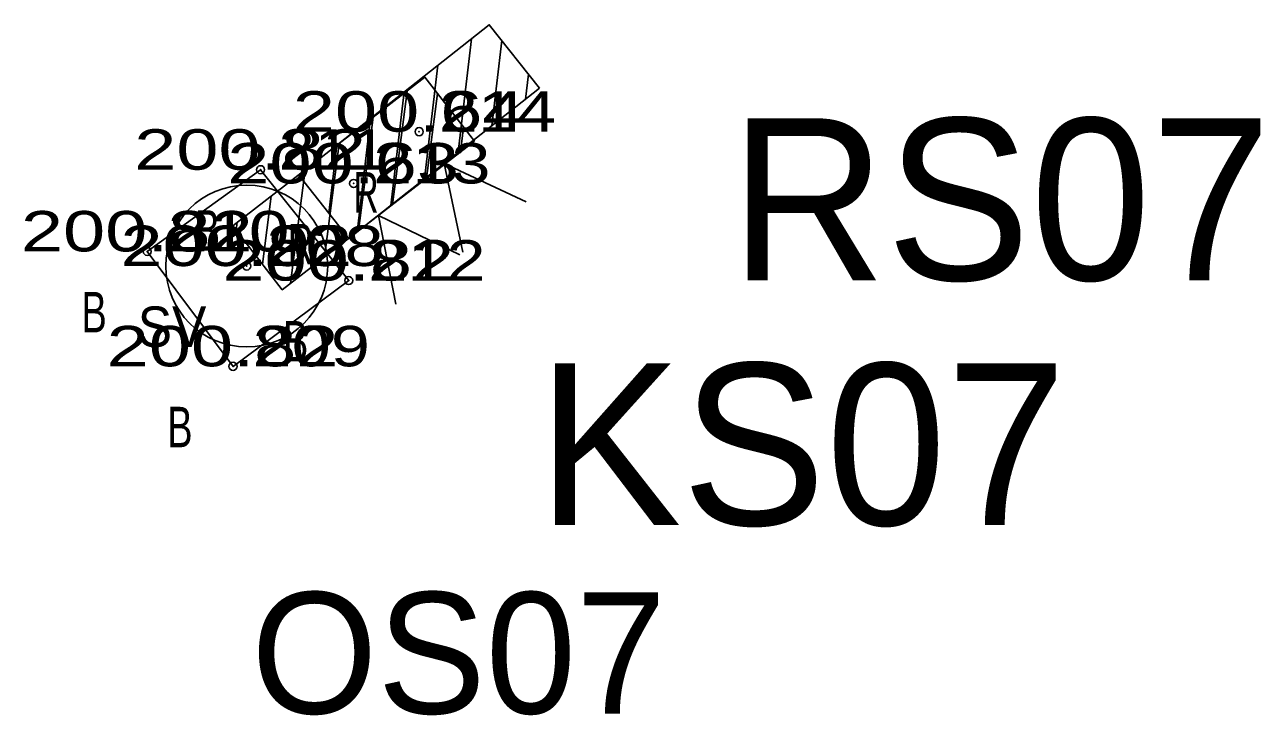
# Model space of a CAD drawing. Extents: x -465254 to -463400, y -1095454 to -1094005.
# Drawn here: x -465102.15 to -465086.89, y -1095346.43 to -1095337.9 of the extents above; entities that cross this region are included whole.
import ezdxf
from ezdxf.enums import TextEntityAlignment as Align

# ---------------------------------------------------------------- set-up
doc = ezdxf.new("R2010")
doc.units = 0
doc.header["$LTSCALE"] = 0.2
doc.header["$PDMODE"] = 32
doc.header["$PDSIZE"] = 0.1
for name, color, linetype in [('1', 7, 'Continuous'), ('2', 7, 'Continuous'), ('3', 7, 'Continuous'), ('4', 7, 'Continuous')]:
    doc.layers.add(name, color=color, linetype=linetype)
for name, color, linetype, lineweight in [('12', 7, 'Continuous', 25), ('25', 7, 'Continuous', 25), ('33', 7, 'Continuous', 25)]:
    doc.layers.add(name, color=color, linetype=linetype, lineweight=lineweight)

msp = doc.modelspace()

# ---------------------------------------------------------------- linework, layer by layer
at = {"layer": '1'}
for p in [(-465097.28, -1095339.22), (-465099.24, -1095339.69), (-465098.09, -1095339.86), (-465100.64, -1095340.7), (-465099.41, -1095340.88), (-465098.15, -1095341.06), (-465099.58, -1095342.12)]:
    msp.add_point(p, dxfattribs=at)
at = {"layer": '12'}
msp.add_lwpolyline([(-465099.24, -1095339.69), (-465098.15, -1095341.06), (-465099.58, -1095342.12), (-465100.64, -1095340.7)], close=True, dxfattribs=at)
at = {"layer": '25'}
msp.add_circle((-465099.41, -1095340.88), 1, dxfattribs=at)
at = {"layer": '33'}
for p, q in [((-465096.632, -1095338.071), (-465096.797, -1095339.475)), ((-465096.257, -1095338.095), (-465096.38, -1095339.146)), ((-465097.048, -1095338.399), (-465097.212, -1095339.804)), ((-465095.928, -1095338.511), (-465095.964, -1095338.818)), ((-465097.464, -1095338.728), (-465097.628, -1095340.132)), ((-465097.43, -1095338.718), (-465097.609, -1095340.121)), ((-465097.055, -1095338.747), (-465097.189, -1095339.796)), ((-465097.88, -1095339.057), (-465098.045, -1095340.462)), ((-465097.849, -1095339.042), (-465098.029, -1095340.445)), ((-465096.731, -1095339.166), (-465096.77, -1095339.472)), ((-465098.268, -1095339.366), (-465098.448, -1095340.769)), ((-465098.296, -1095339.386), (-465098.395, -1095340.228)), ((-465098.688, -1095339.691), (-465098.868, -1095341.093)), ((-465098.712, -1095339.714), (-465098.724, -1095339.813)), ((-465099.108, -1095340.015), (-465099.216, -1095340.856)), ((-465099.527, -1095340.339), (-465099.54, -1095340.437))]:
    msp.add_line(p, q, dxfattribs=at)
for points in [[(-465095.793, -1095338.682), (-465098.147, -1095340.542), (-465098.767, -1095339.758), (-465096.413, -1095337.898)], [(-465095.793, -1095338.682), (-465098.147, -1095340.542), (-465098.767, -1095339.758), (-465096.413, -1095337.898)], [(-465096.597, -1095339.338), (-465098.971, -1095341.173), (-465099.583, -1095340.382), (-465097.209, -1095338.547)], [(-465096.597, -1095339.338), (-465098.971, -1095341.173), (-465099.583, -1095340.382), (-465097.209, -1095338.547)]]:
    msp.add_lwpolyline(points, close=True, dxfattribs=at)
for points in [[(-465095.958, -1095340.087), (-465096.97, -1095339.612), (-465096.742, -1095340.707)], [(-465096.777, -1095340.741), (-465097.784, -1095340.256), (-465097.568, -1095341.353)]]:
    msp.add_lwpolyline(points, dxfattribs=at)

# ---------------------------------------------------------------- texts
at = {"layer": '2'}
for s, width, p in [(' 214', 1.3, (-465097.28, -1095339.22)), (' 211', 1.2, (-465099.24, -1095339.69)), (' 213', 1.3, (-465098.09, -1095339.86)), (' 210', 1.35, (-465100.64, -1095340.7)), (' 208', 1.3, (-465099.41, -1095340.88)), (' 212', 1.3, (-465098.15, -1095341.06)), (' 209', 1.3, (-465099.58, -1095342.12))]:
    msp.add_text(s, height=0.5, dxfattribs=dict(at, width=width)).set_placement(p)
at = {"layer": '25'}
msp.add_text('OS07', height=1.5, dxfattribs=at).set_placement((-465096.7905, -1095346.411), align=Align.CENTER)
at = {"layer": '3', "width": 1.4}
for s, p in [('200.64 ', (-465097.2795, -1095339.22)), ('200.82 ', (-465099.2395, -1095339.69)), ('200.63 ', (-465098.0895, -1095339.86)), ('200.82 ', (-465100.6395, -1095340.7)), ('200.92 ', (-465099.4095, -1095340.88)), ('200.82 ', (-465098.1495, -1095341.06)), ('200.82 ', (-465099.5795, -1095342.12))]:
    msp.add_text(s, height=0.5, dxfattribs=at).set_placement(p, align=Align.CENTER)
at = {"layer": '33'}
for s, p in [('RS07', (-465090.097, -1095341.055)), ('KS07', (-465092.55, -1095344.082))]:
    msp.add_text(s, height=2, dxfattribs=at).set_placement(p, align=Align.CENTER)
at = {"layer": '4'}
for s, width, p in [('R', 0.65, (-465097.78, -1095340.22)), ('B', 0.7, (-465099.74, -1095340.69)), ('R', 0.65, (-465098.59, -1095340.86)), ('B', 0.7, (-465101.14, -1095341.7)), ('SV', 0.95, (-465099.91, -1095341.88)), ('B', 0.7, (-465098.65, -1095342.06)), ('B', 0.7, (-465100.08, -1095343.12))]:
    msp.add_text(s, height=0.5, dxfattribs=dict(at, width=width)).set_placement(p, align=Align.RIGHT)

doc.saveas('drawing.dxf')
